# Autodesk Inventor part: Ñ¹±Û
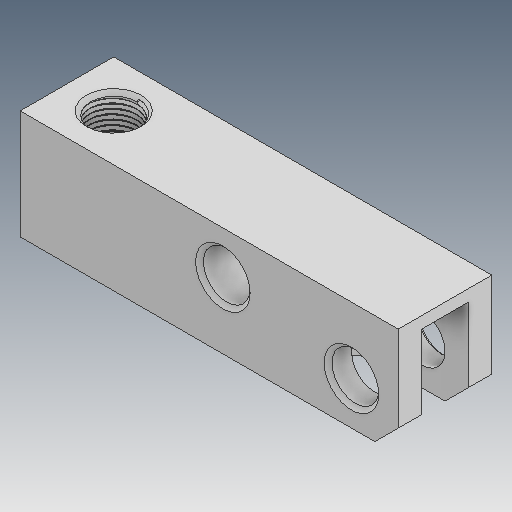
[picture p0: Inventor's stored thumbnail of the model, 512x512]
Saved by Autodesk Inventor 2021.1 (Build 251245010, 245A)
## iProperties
Created: 2019-04
Part Number: Ñ¹±Û
Material: Ogólny
Document SubType Name: Modeling
Designer: user
Density: 1 g/cm^3
Appearance: Domyślna
Author: user
Revision Number: ÈÎºÎ
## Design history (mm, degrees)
feature "ÊäÈë1"
node "Bryła1"
